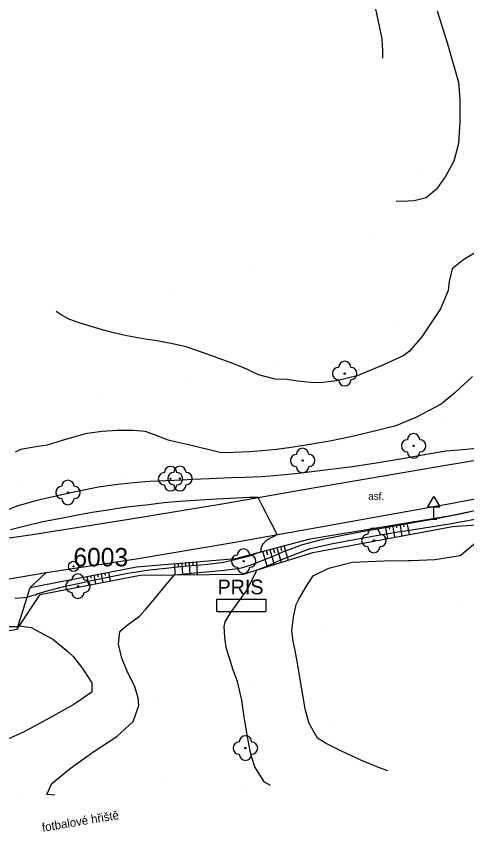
# Model space of a CAD drawing. Extents: x -448957 to -448612, y -1107690 to -1107245.
# Drawn here: x -448813.9 to -448777.1, y -1107412.4 to -1107345.8 of the extents above; entities that cross this region are included whole.
import ezdxf

# ---------------------------------------------------------------- set-up
doc = ezdxf.new("R2010")
doc.units = 0
for name, color, linetype in [('22', 7, 'Continuous'), ('34', 7, 'Continuous'), ('63', 7, 'Continuous'), ('Default', 7, 'Continuous'), ('Vrstva 1', 7, 'Continuous'), ('Vrstva 10', 7, 'Continuous'), ('Vrstva 11', 7, 'Continuous'), ('Vrstva 14', 7, 'Continuous'), ('Vrstva 15', 7, 'Continuous'), ('Vrstva 16', 7, 'Continuous'), ('Vrstva 17', 7, 'Continuous'), ('Vrstva 22', 7, 'Continuous'), ('Vrstva 24', 7, 'Continuous'), ('Vrstva 34', 7, 'Continuous'), ('Vrstva 40', 7, 'Continuous'), ('Vrstva 42', 7, 'Continuous'), ('Vrstva 63', 7, 'Continuous')]:
    doc.layers.add(name, color=color, linetype=linetype)

# ---------------------------------------------------------------- blocks, each defined once
blk = doc.blocks.new('POINT_DISPLAY')
at = {"layer": 'Default'}
blk.add_line((0, 0), (0, 0), dxfattribs=at)
blk = doc.blocks.new('STROM$5')
at = {"layer": '22'}
blk.add_circle((0, 0), 0.5, dxfattribs=at)
for centre, start, end in [((0, 5), 0, 180), ((-5, 0), 90, 270), ((5, 0), 270, 90), ((0, -5), 180, 0)]:
    blk.add_arc(centre, 5, start, end, dxfattribs=at)
blk = doc.blocks.new('DZ$0')
at = {"layer": '34'}
for p, q in [((-5, 10), (0, 18.5)), ((0, 18.5), (5, 10)), ((-5, 10), (5, 10)), ((0, 0), (0, 10)), ((-2.49, 0), (2.49, 0))]:
    blk.add_line(p, q, dxfattribs=at)
blk = doc.blocks.new('PRIS')
at = {"layer": 'Default'}
for p, q in [((-20, 5), (20, 5)), ((-20, -5), (-20, 5)), ((20, 5), (20, -5)), ((-20, -5), (20, -5))]:
    blk.add_line(p, q, dxfattribs=at)
blk.add_text('PRIS', height=12, dxfattribs=at).set_placement((-19.27049, 8.99734))
blk = doc.blocks.new('PPBP$7')
at = {"layer": '63'}
for radius in [4.12, 0.5]:
    blk.add_circle((0, 0), radius, dxfattribs=at)

msp = doc.modelspace()

# ---------------------------------------------------------------- linework, layer by layer
at = {"layer": 'Vrstva 10'}
for p, q in [((-448778.859, -1107382.461), (-448770.794, -1107381.085)), ((-448790.475, -1107384.435), (-448778.859, -1107382.461)), ((-448796.925, -1107385.582), (-448790.475, -1107384.435)), ((-448778.469, -1107385.6), (-448770.221, -1107383.984)), ((-448804.716, -1107386.872), (-448796.925, -1107385.582)), ((-448789.964, -1107387.646), (-448778.469, -1107385.6)), ((-448812.577, -1107388.123), (-448804.716, -1107386.872)), ((-448796.361, -1107388.799), (-448789.964, -1107387.646)), ((-448819.806, -1107389.115), (-448812.577, -1107388.123)), ((-448804.116, -1107390.107), (-448796.361, -1107388.799)), ((-448811.47, -1107391.213), (-448804.116, -1107390.107)), ((-448817.294, -1107392.217), (-448811.47, -1107391.213))]:
    msp.add_line(p, q, dxfattribs=at)
at = {"layer": 'Vrstva 11'}
for p, q in [((-448812.775, -1107392.445), (-448811.47, -1107391.213)), ((-448813.828, -1107395.852), (-448812.775, -1107392.445)), ((-448817.303, -1107396.41), (-448813.828, -1107395.852))]:
    msp.add_line(p, q, dxfattribs=at)
at = {"layer": 'Vrstva 14'}
for p, q in [((-448778.436, -1107386.561), (-448770.128, -1107384.856)), ((-448789.912, -1107388.46), (-448778.436, -1107386.561)), ((-448778.293, -1107387.451), (-448770.163, -1107386.956)), ((-448789.708, -1107389.584), (-448778.293, -1107387.451)), ((-448795.992, -1107390.061), (-448789.912, -1107388.46)), ((-448795.35, -1107391.358), (-448789.708, -1107389.584)), ((-448804.079, -1107390.758), (-448795.992, -1107390.061)), ((-448812.775, -1107392.445), (-448804.079, -1107390.758)), ((-448811.958, -1107393.008), (-448803.785, -1107391.43)), ((-448803.785, -1107391.43), (-448795.35, -1107391.358)), ((-448813.828, -1107395.852), (-448811.958, -1107393.008))]:
    msp.add_line(p, q, dxfattribs=at)
at = {"layer": 'Vrstva 15'}
for p, q in [((-448783.799, -1107387.448), (-448783.623, -1107388.447)), ((-448783.503, -1107387.399), (-448783.453, -1107387.685)), ((-448783.207, -1107387.351), (-448783.033, -1107388.337)), ((-448782.911, -1107387.302), (-448782.862, -1107387.583)), ((-448782.615, -1107387.253), (-448782.444, -1107388.227)), ((-448782.319, -1107387.204), (-448782.27, -1107387.482)), ((-448782.023, -1107387.155), (-448781.854, -1107388.116)), ((-448792.346, -1107389.101), (-448792.246, -1107389.449)), ((-448792.056, -1107389.025), (-448791.713, -1107390.214)), ((-448793.797, -1107389.483), (-448793.43, -1107390.754)), ((-448793.507, -1107389.407), (-448793.402, -1107389.77)), ((-448793.217, -1107389.33), (-448792.858, -1107390.574)), ((-448792.927, -1107389.254), (-448792.824, -1107389.609)), ((-448792.637, -1107389.177), (-448792.285, -1107390.394)), ((-448800.694, -1107390.466), (-448800.682, -1107390.727)), ((-448800.395, -1107390.44), (-448800.349, -1107391.401)), ((-448800.096, -1107390.415), (-448800.083, -1107390.689)), ((-448799.797, -1107390.389), (-448799.749, -1107391.396)), ((-448799.498, -1107390.363), (-448799.484, -1107390.651)), ((-448799.198, -1107390.337), (-448799.149, -1107391.39)), ((-448800.993, -1107390.492), (-448800.95, -1107391.406)), ((-448808.148, -1107391.547), (-448808.013, -1107392.246)), ((-448807.854, -1107391.49), (-448807.815, -1107391.69)), ((-448807.559, -1107391.433), (-448807.424, -1107392.133)), ((-448807.265, -1107391.376), (-448807.226, -1107391.576)), ((-448806.97, -1107391.319), (-448806.835, -1107392.019)), ((-448806.676, -1107391.262), (-448806.637, -1107391.462)), ((-448806.381, -1107391.205), (-448806.246, -1107391.905))]:
    msp.add_line(p, q, dxfattribs=at)
at = {"layer": 'Vrstva 16'}
for points in [[(-448775.84, -1107381.046), (-448777.459, -1107381.197), (-448778.815, -1107381.319), (-448780.585, -1107381.629), (-448782.538, -1107381.97), (-448784.526, -1107382.29), (-448786.465, -1107382.604), (-448788.692, -1107382.877), (-448790.667, -1107383.117), (-448791.697, -1107383.226), (-448792.821, -1107383.343), (-448793.9, -1107383.4), (-448795.26, -1107383.465), (-448796.344, -1107383.502), (-448798.123, -1107383.573), (-448799.485, -1107383.64), (-448800.346, -1107383.693), (-448801.709, -1107383.739), (-448803.009, -1107383.783), (-448804.34, -1107383.892), (-448805.833, -1107384.066), (-448807.18, -1107384.256), (-448809.079, -1107384.627), (-448810.429, -1107384.935), (-448810.758, -1107385.018), (-448812.112, -1107385.31), (-448813.846, -1107385.806), (-448814.768, -1107386.18)], [(-448810.746, -1107409.386), (-448811.403, -1107409.32), (-448811.01, -1107408.423), (-448809.51, -1107407.199), (-448807.652, -1107405.875), (-448805.706, -1107404.588), (-448804.359, -1107403.37), (-448803.904, -1107402.064), (-448803.943, -1107401.449), (-448804.236, -1107400.549), (-448804.888, -1107399.214), (-448805.274, -1107398.192), (-448805.558, -1107397.054), (-448805.462, -1107396.023), (-448804.851, -1107395.507), (-448803.843, -1107394.792), (-448803.382, -1107394.261), (-448803.324, -1107394.205), (-448802.741, -1107393.504), (-448801.589, -1107392.124), (-448800.981, -1107391.406), (-448800.97, -1107391.405), (-448799.62, -1107391.281), (-448797.173, -1107391.043), (-448795.831, -1107390.903), (-448795.421, -1107390.819), (-448794.444, -1107390.48), (-448792.897, -1107389.87), (-448791.957, -1107389.455), (-448791.565, -1107389.305), (-448790.625, -1107388.963), (-448788.892, -1107388.486), (-448786.991, -1107388.11), (-448785.378, -1107387.82), (-448783.468, -1107387.483), (-448781.849, -1107387.192), (-448779.94, -1107386.853), (-448778.386, -1107386.574), (-448777.582, -1107386.398), (-448776.824, -1107386.23)], [(-448814.509, -1107395.615), (-448813.894, -1107395.624), (-448813.753, -1107395.611), (-448813.642, -1107395.57), (-448812.692, -1107395.694), (-448810.921, -1107396.66)], [(-448810.921, -1107396.66), (-448809.687, -1107397.668), (-448809.255, -1107398.064), (-448808.541, -1107398.969), (-448807.731, -1107400.225), (-448807.726, -1107400.978), (-448809.19, -1107401.973), (-448811.411, -1107403.202), (-448813.305, -1107404.233), (-448814.524, -1107404.794)]]:
    msp.add_lwpolyline(points, dxfattribs=at)
at = {"layer": 'Vrstva 17'}
for points in [[(-448784.586, -1107345.24), (-448784.07, -1107347.672), (-448784.021, -1107348.669), (-448784.03, -1107349.245)], [(-448779.545, -1107345.394), (-448778.721, -1107348.083), (-448777.813, -1107351.212), (-448777.709, -1107352.608), (-448777.705, -1107354.444), (-448777.806, -1107356.219), (-448778.211, -1107357.666), (-448778.859, -1107358.85), (-448779.6, -1107359.931), (-448780.443, -1107360.662), (-448781.435, -1107360.887), (-448782.431, -1107360.942), (-448782.902, -1107360.918)], [(-448776.04, -1107364.882), (-448777.394, -1107365.691), (-448778.324, -1107366.433), (-448778.588, -1107367.481), (-448778.673, -1107368.212), (-448779.293, -1107369.7), (-448780.813, -1107371.982), (-448781.806, -1107373.162), (-448782.272, -1107373.502), (-448783.981, -1107374.309), (-448786.086, -1107375.18), (-448787.782, -1107375.581), (-448789.064, -1107375.754), (-448789.898, -1107375.728), (-448790.927, -1107375.6), (-448791.809, -1107375.476), (-448792.772, -1107375.432), (-448794.127, -1107375.082), (-448794.987, -1107374.693), (-448795.131, -1107374.604), (-448796.436, -1107374.085), (-448798.702, -1107373.263), (-448800.042, -1107372.81), (-448801.162, -1107372.558), (-448802.443, -1107372.33), (-448803.386, -1107372.187), (-448804.881, -1107371.902), (-448805.93, -1107371.67), (-448805.957, -1107371.663), (-448806.979, -1107371.394), (-448808.692, -1107370.883), (-448809.624, -1107370.557), (-448810.242, -1107370.202), (-448810.632, -1107369.928)], [(-448776.679, -1107375.235), (-448778.107, -1107376.566), (-448779.237, -1107377.483), (-448781.302, -1107378.57), (-448783.013, -1107379.274), (-448783.147, -1107379.316), (-448784.659, -1107379.689), (-448786.602, -1107380.154), (-448788.317, -1107380.494), (-448790.265, -1107380.842), (-448791.661, -1107381.049), (-448792.687, -1107381.184), (-448793.835, -1107381.291), (-448794.869, -1107381.374), (-448796.137, -1107381.428), (-448797.177, -1107381.465), (-448798.153, -1107381.221), (-448799.838, -1107380.813), (-448800.817, -1107380.574), (-448801.512, -1107380.425), (-448802.409, -1107380.063), (-448803.362, -1107379.715), (-448804.371, -1107379.629), (-448805.667, -1107379.621), (-448806.906, -1107379.717), (-448808.281, -1107379.906), (-448810.145, -1107380.439), (-448811.37, -1107380.821), (-448812.441, -1107381.003), (-448813.55, -1107381.175), (-448813.996, -1107381.396)], [(-448814.004, -1107393.302), (-448813.221, -1107393.245), (-448813.016, -1107393.225), (-448812.941, -1107393.204), (-448812.758, -1107393.149), (-448812.514, -1107393.079), (-448812.334, -1107393.031), (-448812.204, -1107392.959), (-448811.38, -1107392.706), (-448810.019, -1107392.364), (-448808.987, -1107392.129), (-448807.613, -1107391.842), (-448806.154, -1107391.552), (-448804.799, -1107391.272), (-448803.035, -1107390.991), (-448801.697, -1107390.852), (-448800.217, -1107390.712), (-448798.866, -1107390.599), (-448798.285, -1107390.545), (-448796.959, -1107390.372), (-448794.949, -1107389.886), (-448793.977, -1107389.536), (-448793.947, -1107389.525), (-448793.931, -1107389.518), (-448793.907, -1107389.307), (-448793.868, -1107389.07), (-448793.732, -1107388.849), (-448793.514, -1107388.599), (-448793.265, -1107388.449), (-448792.858, -1107388.239), (-448792.601, -1107388.121), (-448792.684, -1107387.977), (-448792.943, -1107387.47), (-448793.253, -1107386.87), (-448793.516, -1107386.365), (-448793.831, -1107385.762), (-448794.083, -1107385.257), (-448794.149, -1107385.088), (-448794.465, -1107385.095), (-448794.883, -1107385.104), (-448795.967, -1107385.147), (-448797.548, -1107385.222), (-448798.884, -1107385.307), (-448800.516, -1107385.433), (-448801.83, -1107385.545), (-448803.317, -1107385.71), (-448804.624, -1107385.865), (-448805.08, -1107385.926), (-448806.391, -1107386.127), (-448807.699, -1107386.334), (-448809.004, -1107386.574), (-448810.39, -1107386.832), (-448811.739, -1107387.093), (-448813.295, -1107387.468), (-448814.359, -1107387.741)], [(-448793.159, -1107408.592), (-448793.648, -1107408.318), (-448794.441, -1107407.078), (-448794.77, -1107406.042), (-448794.822, -1107405.771), (-448795.051, -1107404.465), (-448795.297, -1107402.986), (-448795.495, -1107401.645), (-448795.861, -1107400.112), (-448796.195, -1107399.191), (-448796.505, -1107398.195), (-448796.764, -1107397.351), (-448796.885, -1107396.461), (-448796.94, -1107395.61), (-448796.842, -1107395.241), (-448796.441, -1107394.555), (-448795.64, -1107393.41), (-448795.116, -1107392.713), (-448795.071, -1107392.627), (-448794.643, -1107391.794), (-448794.243, -1107391.01), (-448793.862, -1107390.854), (-448793.096, -1107390.53), (-448792.174, -1107390.133), (-448790.856, -1107389.604), (-448789.927, -1107389.246), (-448788.08, -1107388.861), (-448786.179, -1107388.493), (-448784.666, -1107388.231), (-448782.757, -1107387.912), (-448782.011, -1107387.788), (-448780.098, -1107387.478), (-448778.224, -1107387.18), (-448778.018, -1107387.147), (-448777.344, -1107387.032), (-448776.22, -1107386.824)], [(-448783.596, -1107407.41), (-448784.355, -1107407.134), (-448785.78, -1107406.529), (-448787.354, -1107405.794), (-448788.607, -1107405.167), (-448789.326, -1107404.722), (-448789.991, -1107403.531), (-448790.299, -1107402.479), (-448790.321, -1107402.357), (-448790.513, -1107401.19), (-448790.724, -1107399.941), (-448790.924, -1107398.78), (-448791.155, -1107397.591), (-448791.298, -1107396.814), (-448791.408, -1107395.956), (-448791.267, -1107394.858), (-448791.058, -1107393.826), (-448790.85, -1107393.395), (-448790.264, -1107392.405), (-448789.677, -1107391.488), (-448788.388, -1107390.867), (-448786.498, -1107390.369), (-448783.879, -1107390.264), (-448781.939, -1107390.235), (-448781.677, -1107390.23), (-448779.741, -1107390.164), (-448777.681, -1107389.821), (-448776.435, -1107388.801)]]:
    msp.add_lwpolyline(points, dxfattribs=at)

# ---------------------------------------------------------------- block references
at = {"layer": 'Vrstva 1', "xscale": 0.1, "yscale": 0.10000000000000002}
for p in [(-448787.101, -1107374.988), (-448778.859, -1107382.461), (-448790.475, -1107384.435), (-448796.925, -1107385.582), (-448778.469, -1107385.6), (-448804.716, -1107386.872), (-448778.436, -1107386.561), (-448789.964, -1107387.646), (-448778.293, -1107387.451), (-448812.577, -1107388.123), (-448789.912, -1107388.46), (-448796.361, -1107388.799), (-448789.708, -1107389.584), (-448804.116, -1107390.107), (-448795.992, -1107390.061), (-448804.079, -1107390.758), (-448804.079, -1107390.758), (-448811.47, -1107391.213), (-448811.47, -1107391.213), (-448803.785, -1107391.43), (-448795.35, -1107391.358), (-448812.775, -1107392.445), (-448812.775, -1107392.445), (-448811.958, -1107393.008), (-448811.958, -1107393.008), (-448813.828, -1107395.852), (-448813.828, -1107395.852)]:
    msp.add_blockref('POINT_DISPLAY', p, dxfattribs=at)
at = {"layer": 'Vrstva 14', "xscale": 0.1, "yscale": 0.10000000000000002}
for p in [(-448781.263, -1107358.622), (-448784.783, -1107363.554), (-448794.739, -1107366.48), (-448800.951, -1107368.202), (-448809.604, -1107370.012), (-448783.108, -1107370.996), (-448792.5, -1107374.073), (-448800.002, -1107375.442), (-448807.324, -1107376.837), (-448779.281, -1107378.685), (-448791.046, -1107380.488), (-448797.177, -1107381.465), (-448813.759, -1107383.695), (-448805.256, -1107383.352), (-448777.557, -1107393.826), (-448803.024, -1107395.674), (-448794.728, -1107395.359), (-448788.999, -1107396), (-448794.414, -1107400.471), (-448802.572, -1107401.84), (-448788.186, -1107403.287), (-448801.97, -1107407.836), (-448795.127, -1107408.835), (-448813.75, -1107409.492)]:
    msp.add_blockref('POINT_DISPLAY', p, dxfattribs=at)
at = {"layer": 'Vrstva 22', "xscale": 0.1, "yscale": 0.10000000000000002}
for p in [(-448787.101, -1107374.988), (-448781.477, -1107380.885), (-448790.537, -1107382.083), (-448801.312, -1107383.567), (-448800.543, -1107383.553), (-448809.685, -1107384.687), (-448784.719, -1107388.6), (-448795.35, -1107390.289), (-448808.871, -1107392.335), (-448795.202, -1107405.541)]:
    msp.add_blockref('STROM$5', p, dxfattribs=at)
at = {"layer": 'Vrstva 24', "xscale": 0.1, "yscale": 0.10000000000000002}
msp.add_blockref('PRIS', (-448795.548, -1107393.896), dxfattribs=at)
at = {"layer": 'Vrstva 34', "xscale": 0.1, "yscale": 0.10000000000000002}
msp.add_blockref('DZ$0', (-448779.827, -1107386.864), dxfattribs=at)
at = {"layer": 'Vrstva 63', "xscale": 0.1, "yscale": 0.10000000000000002}
msp.add_blockref('PPBP$7', (-448809.234, -1107390.716), dxfattribs=at)

# ---------------------------------------------------------------- texts
at = {"layer": 'Vrstva 40'}
msp.add_text('asf.', height=0.6, dxfattribs=at).set_placement((-448785.182, -1107385.289))
at = {"layer": 'Vrstva 42'}
msp.add_text('fotbalové hřiště', height=0.7, rotation=9.537, dxfattribs=at).set_placement((-448811.741, -1107412.375))
at = {"layer": 'Vrstva 63'}
msp.add_text('6003', height=1.5, dxfattribs=at).set_placement((-448809.234, -1107390.716))

doc.saveas('drawing.dxf')
